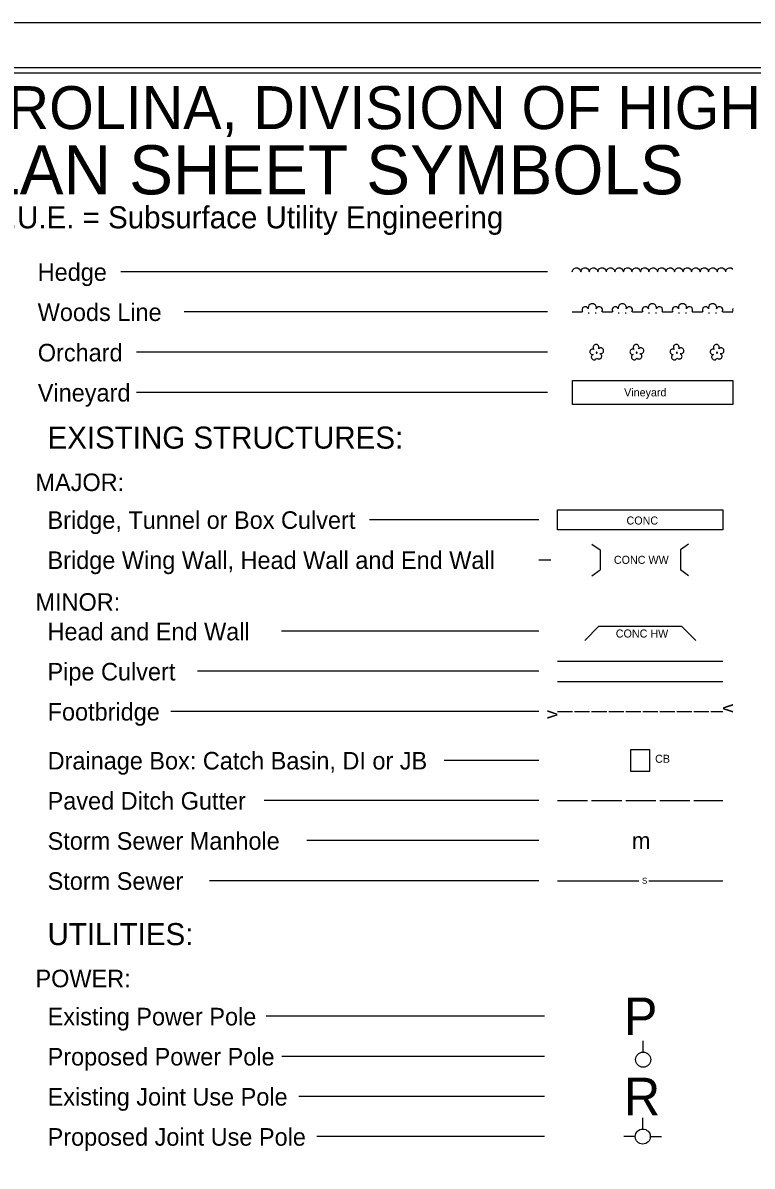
# Model space of a CAD drawing. Extents: x 872928 to 873392, y 373968 to 374173.
# Drawn here: x 872946.93 to 872954.2, y 374081.15 to 374092.55 of the extents above; entities that cross this region are included whole.
import ezdxf

# ---------------------------------------------------------------- set-up
doc = ezdxf.new("R2010")
doc.units = 0
for name, color, linetype in [('Sheet Cutting Line CELL', 7, 'Continuous'), ('Sheet Plot Border Inside CELL', 7, 'Continuous'), ('Sheet Plot Border Outside CELL', 7, 'Continuous'), ('Sheet Symbology CELL', 7, 'Continuous')]:
    doc.layers.add(name, color=color, linetype=linetype)

msp = doc.modelspace()

# ---------------------------------------------------------------- linework, layer by layer
at = {"layer": 'Sheet Cutting Line CELL'}
msp.add_line((872962.151, 374092.547), (872928.471, 374092.547), dxfattribs=at)
at = {"layer": 'Sheet Plot Border Inside CELL'}
msp.add_lwpolyline([(872928.731, 374070.996), (872962.061, 374070.996), (872962.061, 374092.098), (872928.731, 374092.098)], close=True, dxfattribs=at)
at = {"layer": 'Sheet Plot Border Outside CELL'}
msp.add_lwpolyline([(872928.471, 374070.547), (872962.151, 374070.547), (872962.151, 374092.547), (872928.471, 374092.547)], close=True, dxfattribs=at)
at = {"layer": 'Sheet Symbology CELL'}
for p, q in [((872952.157, 374090.064), (872947.903, 374090.064)), ((872952.405, 374090.064), (872952.411, 374090.083)), ((872952.411, 374090.083), (872952.423, 374090.096)), ((872952.423, 374090.096), (872952.439, 374090.105)), ((872952.439, 374090.105), (872952.458, 374090.105)), ((872952.458, 374090.105), (872952.474, 374090.095)), ((872952.474, 374090.095), (872952.485, 374090.082)), ((872952.485, 374090.082), (872952.489, 374090.065)), ((872952.49, 374090.064), (872952.496, 374090.083)), ((872952.496, 374090.083), (872952.508, 374090.096)), ((872952.508, 374090.096), (872952.524, 374090.105)), ((872952.524, 374090.105), (872952.543, 374090.105)), ((872952.543, 374090.105), (872952.559, 374090.095)), ((872952.559, 374090.095), (872952.57, 374090.082)), ((872952.57, 374090.082), (872952.574, 374090.065)), ((872952.575, 374090.064), (872952.581, 374090.083)), ((872952.581, 374090.083), (872952.593, 374090.096)), ((872952.593, 374090.096), (872952.609, 374090.105)), ((872952.609, 374090.105), (872952.628, 374090.105)), ((872952.628, 374090.105), (872952.644, 374090.095)), ((872952.644, 374090.095), (872952.655, 374090.082)), ((872952.655, 374090.082), (872952.659, 374090.065)), ((872952.66, 374090.064), (872952.666, 374090.083)), ((872952.666, 374090.083), (872952.678, 374090.096)), ((872952.678, 374090.096), (872952.694, 374090.105)), ((872952.694, 374090.105), (872952.713, 374090.105)), ((872952.713, 374090.105), (872952.729, 374090.095)), ((872952.729, 374090.095), (872952.74, 374090.082)), ((872952.74, 374090.082), (872952.744, 374090.065)), ((872952.745, 374090.064), (872952.751, 374090.083)), ((872952.751, 374090.083), (872952.763, 374090.096)), ((872952.763, 374090.096), (872952.779, 374090.105)), ((872952.779, 374090.105), (872952.798, 374090.105)), ((872952.798, 374090.105), (872952.814, 374090.095)), ((872952.814, 374090.095), (872952.825, 374090.082)), ((872952.825, 374090.082), (872952.829, 374090.065)), ((872952.83, 374090.064), (872952.836, 374090.083)), ((872952.836, 374090.083), (872952.848, 374090.096)), ((872952.848, 374090.096), (872952.864, 374090.105)), ((872952.864, 374090.105), (872952.883, 374090.105)), ((872952.883, 374090.105), (872952.899, 374090.095)), ((872952.899, 374090.095), (872952.91, 374090.082)), ((872952.91, 374090.082), (872952.914, 374090.065)), ((872952.915, 374090.064), (872952.921, 374090.083)), ((872952.921, 374090.083), (872952.933, 374090.096)), ((872952.933, 374090.096), (872952.949, 374090.105)), ((872952.949, 374090.105), (872952.968, 374090.105)), ((872952.968, 374090.105), (872952.984, 374090.095)), ((872952.984, 374090.095), (872952.995, 374090.082)), ((872952.995, 374090.082), (872952.999, 374090.065)), ((872953, 374090.064), (872953.006, 374090.083)), ((872953.006, 374090.083), (872953.018, 374090.096)), ((872953.018, 374090.096), (872953.034, 374090.105)), ((872953.034, 374090.105), (872953.053, 374090.105)), ((872953.053, 374090.105), (872953.069, 374090.095)), ((872953.069, 374090.095), (872953.08, 374090.082)), ((872953.08, 374090.082), (872953.084, 374090.065)), ((872953.085, 374090.064), (872953.091, 374090.083)), ((872953.091, 374090.083), (872953.103, 374090.096)), ((872953.103, 374090.096), (872953.119, 374090.105)), ((872953.119, 374090.105), (872953.138, 374090.105)), ((872953.138, 374090.105), (872953.154, 374090.095)), ((872953.154, 374090.095), (872953.165, 374090.082)), ((872953.165, 374090.082), (872953.169, 374090.065)), ((872953.17, 374090.064), (872953.176, 374090.083)), ((872953.176, 374090.083), (872953.188, 374090.096)), ((872953.188, 374090.096), (872953.204, 374090.105)), ((872953.204, 374090.105), (872953.223, 374090.105)), ((872953.223, 374090.105), (872953.239, 374090.095)), ((872953.239, 374090.095), (872953.25, 374090.082)), ((872953.25, 374090.082), (872953.254, 374090.065)), ((872953.255, 374090.064), (872953.261, 374090.083)), ((872953.261, 374090.083), (872953.273, 374090.096)), ((872953.273, 374090.096), (872953.289, 374090.105)), ((872953.289, 374090.105), (872953.308, 374090.105)), ((872953.308, 374090.105), (872953.324, 374090.095)), ((872953.324, 374090.095), (872953.335, 374090.082)), ((872953.335, 374090.082), (872953.339, 374090.065)), ((872953.34, 374090.064), (872953.346, 374090.083)), ((872953.346, 374090.083), (872953.358, 374090.096)), ((872953.358, 374090.096), (872953.374, 374090.105)), ((872953.374, 374090.105), (872953.393, 374090.105)), ((872953.393, 374090.105), (872953.409, 374090.095)), ((872953.409, 374090.095), (872953.42, 374090.082)), ((872953.42, 374090.082), (872953.424, 374090.065)), ((872953.425, 374090.064), (872953.431, 374090.083)), ((872953.431, 374090.083), (872953.443, 374090.096)), ((872953.443, 374090.096), (872953.459, 374090.105)), ((872953.459, 374090.105), (872953.478, 374090.105)), ((872953.478, 374090.105), (872953.494, 374090.095)), ((872953.494, 374090.095), (872953.505, 374090.082)), ((872953.505, 374090.082), (872953.509, 374090.065)), ((872953.51, 374090.064), (872953.516, 374090.083)), ((872953.516, 374090.083), (872953.528, 374090.096)), ((872953.528, 374090.096), (872953.544, 374090.105)), ((872953.544, 374090.105), (872953.563, 374090.105)), ((872953.563, 374090.105), (872953.579, 374090.095)), ((872953.579, 374090.095), (872953.59, 374090.082)), ((872953.59, 374090.082), (872953.594, 374090.065)), ((872953.595, 374090.064), (872953.601, 374090.083)), ((872953.601, 374090.083), (872953.613, 374090.096)), ((872953.613, 374090.096), (872953.629, 374090.105)), ((872953.629, 374090.105), (872953.648, 374090.105)), ((872953.648, 374090.105), (872953.664, 374090.095)), ((872953.664, 374090.095), (872953.675, 374090.082)), ((872953.675, 374090.082), (872953.679, 374090.065)), ((872953.68, 374090.064), (872953.686, 374090.083)), ((872953.686, 374090.083), (872953.698, 374090.096)), ((872953.698, 374090.096), (872953.714, 374090.105)), ((872953.714, 374090.105), (872953.733, 374090.105)), ((872953.733, 374090.105), (872953.749, 374090.095)), ((872953.749, 374090.095), (872953.76, 374090.082)), ((872953.76, 374090.082), (872953.764, 374090.065)), ((872953.765, 374090.064), (872953.771, 374090.083)), ((872953.771, 374090.083), (872953.783, 374090.096)), ((872953.783, 374090.096), (872953.799, 374090.105)), ((872953.799, 374090.105), (872953.818, 374090.105)), ((872953.818, 374090.105), (872953.834, 374090.095)), ((872953.834, 374090.095), (872953.845, 374090.082)), ((872953.845, 374090.082), (872953.849, 374090.065)), ((872953.85, 374090.064), (872953.856, 374090.083)), ((872953.856, 374090.083), (872953.868, 374090.096)), ((872953.868, 374090.096), (872953.884, 374090.105)), ((872953.884, 374090.105), (872953.903, 374090.105)), ((872953.903, 374090.105), (872953.919, 374090.095)), ((872953.919, 374090.095), (872953.93, 374090.082)), ((872953.93, 374090.082), (872953.934, 374090.065)), ((872953.935, 374090.064), (872953.941, 374090.083)), ((872953.941, 374090.083), (872953.953, 374090.096)), ((872953.953, 374090.096), (872953.969, 374090.105)), ((872953.969, 374090.105), (872953.988, 374090.105)), ((872953.988, 374090.105), (872954.004, 374090.095)), ((872954.004, 374090.095), (872954.005, 374090.094)), ((872952.157, 374089.664), (872948.534, 374089.664)), ((872952.405, 374089.664), (872952.505, 374089.664)), ((872952.705, 374089.664), (872952.805, 374089.664)), ((872953.005, 374089.664), (872953.105, 374089.664)), ((872953.305, 374089.664), (872953.405, 374089.664)), ((872953.605, 374089.664), (872953.705, 374089.664)), ((872953.905, 374089.664), (872954.005, 374089.664)), ((872952.564, 374089.654), (872952.574, 374089.654)), ((872952.634, 374089.654), (872952.644, 374089.654)), ((872952.864, 374089.654), (872952.874, 374089.654)), ((872952.934, 374089.654), (872952.944, 374089.654)), ((872953.164, 374089.654), (872953.174, 374089.654)), ((872953.234, 374089.654), (872953.244, 374089.654)), ((872953.464, 374089.654), (872953.474, 374089.654)), ((872953.534, 374089.654), (872953.544, 374089.654)), ((872953.764, 374089.654), (872953.774, 374089.654)), ((872953.834, 374089.654), (872953.844, 374089.654)), ((872952.158, 374089.262), (872948.059, 374089.262)), ((872952.158, 374088.862), (872948.059, 374088.862)), ((872952.072, 374087.592), (872950.383, 374087.592)), ((872952.601, 374087.349), (872952.683, 374087.292)), ((872952.683, 374087.292), (872952.683, 374087.092)), ((872953.565, 374087.349), (872953.483, 374087.292)), ((872953.483, 374087.292), (872953.483, 374087.092)), ((872952.072, 374087.192), (872952.191, 374087.192)), ((872952.601, 374087.034), (872952.683, 374087.092)), ((872953.565, 374087.034), (872953.483, 374087.092)), ((872952.072, 374086.48), (872949.506, 374086.48)), ((872952.529, 374086.389), (872952.67, 374086.53)), ((872952.67, 374086.53), (872953.495, 374086.53)), ((872953.495, 374086.53), (872953.637, 374086.389)), ((872952.258, 374086.18), (872953.908, 374086.18)), ((872952.072, 374086.08), (872948.668, 374086.08)), ((872952.258, 374085.98), (872953.908, 374085.98)), ((872952.072, 374085.68), (872948.402, 374085.68)), ((872952.258, 374085.68), (872952.408, 374085.68)), ((872952.428, 374085.68), (872952.578, 374085.68)), ((872952.598, 374085.68), (872952.748, 374085.68)), ((872952.768, 374085.68), (872952.918, 374085.68)), ((872952.938, 374085.68), (872953.088, 374085.68)), ((872953.108, 374085.68), (872953.258, 374085.68)), ((872953.278, 374085.68), (872953.428, 374085.68)), ((872953.448, 374085.68), (872953.598, 374085.68)), ((872953.618, 374085.68), (872953.768, 374085.68)), ((872953.788, 374085.68), (872953.908, 374085.68)), ((872952.072, 374085.192), (872951.128, 374085.192)), ((872952.072, 374084.792), (872949.333, 374084.792)), ((872952.258, 374084.792), (872952.558, 374084.792)), ((872952.598, 374084.792), (872952.898, 374084.792)), ((872952.938, 374084.792), (872953.238, 374084.792)), ((872953.278, 374084.792), (872953.578, 374084.792)), ((872953.618, 374084.792), (872953.908, 374084.792)), ((872952.072, 374084.392), (872949.758, 374084.392)), ((872952.072, 374083.992), (872948.788, 374083.992)), ((872952.258, 374083.992), (872953.068, 374083.992)), ((872953.168, 374083.992), (872953.908, 374083.992)), ((872952.127, 374082.64), (872949.353, 374082.64)), ((872953.112, 374082.282), (872953.112, 374082.395)), ((872952.127, 374082.24), (872949.509, 374082.24)), ((872952.127, 374081.84), (872949.677, 374081.84)), ((872953.108, 374081.515), (872953.108, 374081.628)), ((872952.127, 374081.44), (872949.857, 374081.44)), ((872953.033, 374081.44), (872952.92, 374081.44)), ((872953.183, 374081.44), (872953.295, 374081.44))]:
    msp.add_line(p, q, dxfattribs=at)
for points in [[(872961.811, 374092.047), (872931.811, 374092.047), (872931.811, 374071.068), (872961.811, 374071.068)], [(872952.986, 374085.085), (872953.179, 374085.085), (872953.179, 374085.298), (872952.986, 374085.298)]]:
    msp.add_lwpolyline(points, close=True, dxfattribs=at)
for points in [[(872952.667, 374089.297), (872952.67, 374089.303), (872952.671, 374089.309), (872952.67, 374089.315), (872952.669, 374089.321), (872952.666, 374089.326), (872952.663, 374089.331), (872952.658, 374089.335), (872952.653, 374089.338), (872952.646, 374089.34), (872952.641, 374089.34), (872952.635, 374089.339), (872952.629, 374089.337), (872952.624, 374089.334), (872952.619, 374089.33), (872952.616, 374089.324), (872952.614, 374089.319), (872952.613, 374089.313), (872952.613, 374089.307), (872952.614, 374089.301), (872952.617, 374089.296), (872952.621, 374089.29), (872952.616, 374089.293), (872952.61, 374089.294), (872952.604, 374089.294), (872952.599, 374089.292), (872952.594, 374089.29), (872952.589, 374089.286), (872952.585, 374089.282), (872952.582, 374089.277), (872952.581, 374089.272), (872952.58, 374089.265), (872952.581, 374089.26), (872952.583, 374089.255), (872952.587, 374089.25), (872952.59, 374089.246), (872952.595, 374089.243), (872952.601, 374089.24), (872952.606, 374089.239), (872952.612, 374089.239), (872952.607, 374089.237), (872952.602, 374089.233), (872952.599, 374089.229), (872952.597, 374089.223), (872952.595, 374089.217), (872952.595, 374089.212), (872952.596, 374089.206), (872952.599, 374089.201), (872952.602, 374089.196), (872952.606, 374089.192), (872952.611, 374089.189), (872952.616, 374089.187), (872952.622, 374089.187), (872952.628, 374089.187), (872952.633, 374089.188), (872952.638, 374089.192), (872952.643, 374089.195), (872952.648, 374089.204)], [(872953.067, 374089.297), (872953.07, 374089.303), (872953.071, 374089.309), (872953.07, 374089.315), (872953.069, 374089.321), (872953.066, 374089.326), (872953.063, 374089.331), (872953.058, 374089.335), (872953.053, 374089.338), (872953.046, 374089.34), (872953.041, 374089.34), (872953.035, 374089.339), (872953.029, 374089.337), (872953.024, 374089.334), (872953.019, 374089.33), (872953.016, 374089.324), (872953.014, 374089.319), (872953.013, 374089.313), (872953.013, 374089.307), (872953.014, 374089.301), (872953.017, 374089.296), (872953.021, 374089.29), (872953.016, 374089.293), (872953.01, 374089.294), (872953.004, 374089.294), (872952.999, 374089.292), (872952.994, 374089.29), (872952.989, 374089.286), (872952.985, 374089.282), (872952.982, 374089.277), (872952.981, 374089.272), (872952.98, 374089.265), (872952.981, 374089.26), (872952.983, 374089.255), (872952.987, 374089.25), (872952.99, 374089.246), (872952.995, 374089.243), (872953.001, 374089.24), (872953.006, 374089.239), (872953.012, 374089.239), (872953.007, 374089.237), (872953.002, 374089.233), (872952.999, 374089.229), (872952.997, 374089.223), (872952.995, 374089.217), (872952.995, 374089.212), (872952.996, 374089.206), (872952.999, 374089.201), (872953.002, 374089.196), (872953.006, 374089.192), (872953.011, 374089.189), (872953.016, 374089.187), (872953.022, 374089.187), (872953.028, 374089.187), (872953.033, 374089.188), (872953.038, 374089.192), (872953.043, 374089.195), (872953.048, 374089.204)], [(872953.467, 374089.297), (872953.47, 374089.303), (872953.471, 374089.309), (872953.47, 374089.315), (872953.469, 374089.321), (872953.466, 374089.326), (872953.463, 374089.331), (872953.458, 374089.335), (872953.453, 374089.338), (872953.446, 374089.34), (872953.441, 374089.34), (872953.435, 374089.339), (872953.429, 374089.337), (872953.424, 374089.334), (872953.419, 374089.33), (872953.416, 374089.324), (872953.414, 374089.319), (872953.413, 374089.313), (872953.413, 374089.307), (872953.414, 374089.301), (872953.417, 374089.296), (872953.421, 374089.29), (872953.416, 374089.293), (872953.41, 374089.294), (872953.404, 374089.294), (872953.399, 374089.292), (872953.394, 374089.29), (872953.389, 374089.286), (872953.385, 374089.282), (872953.382, 374089.277), (872953.381, 374089.272), (872953.38, 374089.265), (872953.381, 374089.26), (872953.383, 374089.255), (872953.387, 374089.25), (872953.39, 374089.246), (872953.395, 374089.243), (872953.401, 374089.24), (872953.406, 374089.239), (872953.412, 374089.239), (872953.407, 374089.237), (872953.402, 374089.233), (872953.399, 374089.229), (872953.397, 374089.223), (872953.395, 374089.217), (872953.395, 374089.212), (872953.396, 374089.206), (872953.399, 374089.201), (872953.402, 374089.196), (872953.406, 374089.192), (872953.411, 374089.189), (872953.416, 374089.187), (872953.422, 374089.187), (872953.428, 374089.187), (872953.433, 374089.188), (872953.438, 374089.192), (872953.443, 374089.195), (872953.448, 374089.204)], [(872953.867, 374089.297), (872953.87, 374089.303), (872953.871, 374089.309), (872953.87, 374089.315), (872953.869, 374089.321), (872953.866, 374089.326), (872953.863, 374089.331), (872953.858, 374089.335), (872953.853, 374089.338), (872953.846, 374089.34), (872953.841, 374089.34), (872953.835, 374089.339), (872953.829, 374089.337), (872953.824, 374089.334), (872953.819, 374089.33), (872953.816, 374089.324), (872953.814, 374089.319), (872953.813, 374089.313), (872953.813, 374089.307), (872953.814, 374089.301), (872953.817, 374089.296), (872953.821, 374089.29), (872953.816, 374089.293), (872953.81, 374089.294), (872953.804, 374089.294), (872953.799, 374089.292), (872953.794, 374089.29), (872953.789, 374089.286), (872953.785, 374089.282), (872953.782, 374089.277), (872953.781, 374089.272), (872953.78, 374089.265), (872953.781, 374089.26), (872953.783, 374089.255), (872953.787, 374089.25), (872953.79, 374089.246), (872953.795, 374089.243), (872953.801, 374089.24), (872953.806, 374089.239), (872953.812, 374089.239), (872953.807, 374089.237), (872953.802, 374089.233), (872953.799, 374089.229), (872953.797, 374089.223), (872953.795, 374089.217), (872953.795, 374089.212), (872953.796, 374089.206), (872953.799, 374089.201), (872953.802, 374089.196), (872953.806, 374089.192), (872953.811, 374089.189), (872953.816, 374089.187), (872953.822, 374089.187), (872953.828, 374089.187), (872953.833, 374089.188), (872953.838, 374089.192), (872953.843, 374089.195), (872953.848, 374089.204)], [(872952.65, 374089.262), (872952.647, 374089.262), (872952.645, 374089.261), (872952.643, 374089.26), (872952.643, 374089.257), (872952.643, 374089.255), (872952.645, 374089.253), (872952.648, 374089.253), (872952.65, 374089.253), (872952.652, 374089.255), (872952.653, 374089.258), (872952.652, 374089.26), (872952.65, 374089.262)], [(872952.648, 374089.204), (872952.66, 374089.197), (872952.666, 374089.195), (872952.672, 374089.194), (872952.678, 374089.195), (872952.683, 374089.197), (872952.688, 374089.2), (872952.693, 374089.204), (872952.696, 374089.209), (872952.698, 374089.214), (872952.7, 374089.22), (872952.699, 374089.226), (872952.698, 374089.232), (872952.694, 374089.238), (872952.691, 374089.242), (872952.686, 374089.245), (872952.68, 374089.248), (872952.686, 374089.247), (872952.693, 374089.247), (872952.698, 374089.249), (872952.704, 374089.252), (872952.709, 374089.255), (872952.713, 374089.26), (872952.716, 374089.266), (872952.717, 374089.272), (872952.718, 374089.278), (872952.717, 374089.284), (872952.715, 374089.29), (872952.711, 374089.295), (872952.706, 374089.3), (872952.701, 374089.303), (872952.695, 374089.305), (872952.689, 374089.306), (872952.683, 374089.306), (872952.677, 374089.304), (872952.672, 374089.301), (872952.667, 374089.297)], [(872953.05, 374089.262), (872953.047, 374089.262), (872953.045, 374089.261), (872953.043, 374089.26), (872953.043, 374089.257), (872953.043, 374089.255), (872953.045, 374089.253), (872953.048, 374089.253), (872953.05, 374089.253), (872953.052, 374089.255), (872953.053, 374089.258), (872953.052, 374089.26), (872953.05, 374089.262)], [(872953.048, 374089.204), (872953.06, 374089.197), (872953.066, 374089.195), (872953.072, 374089.194), (872953.078, 374089.195), (872953.083, 374089.197), (872953.088, 374089.2), (872953.093, 374089.204), (872953.096, 374089.209), (872953.098, 374089.214), (872953.1, 374089.22), (872953.099, 374089.226), (872953.098, 374089.232), (872953.094, 374089.238), (872953.091, 374089.242), (872953.086, 374089.245), (872953.08, 374089.248), (872953.086, 374089.247), (872953.093, 374089.247), (872953.098, 374089.249), (872953.104, 374089.252), (872953.109, 374089.255), (872953.113, 374089.26), (872953.116, 374089.266), (872953.117, 374089.272), (872953.118, 374089.278), (872953.117, 374089.284), (872953.115, 374089.29), (872953.111, 374089.295), (872953.106, 374089.3), (872953.101, 374089.303), (872953.095, 374089.305), (872953.089, 374089.306), (872953.083, 374089.306), (872953.077, 374089.304), (872953.072, 374089.301), (872953.067, 374089.297)], [(872953.45, 374089.262), (872953.447, 374089.262), (872953.445, 374089.261), (872953.443, 374089.26), (872953.443, 374089.257), (872953.443, 374089.255), (872953.445, 374089.253), (872953.448, 374089.253), (872953.45, 374089.253), (872953.452, 374089.255), (872953.453, 374089.258), (872953.452, 374089.26), (872953.45, 374089.262)], [(872953.448, 374089.204), (872953.46, 374089.197), (872953.466, 374089.195), (872953.472, 374089.194), (872953.478, 374089.195), (872953.483, 374089.197), (872953.488, 374089.2), (872953.493, 374089.204), (872953.496, 374089.209), (872953.498, 374089.214), (872953.5, 374089.22), (872953.499, 374089.226), (872953.498, 374089.232), (872953.494, 374089.238), (872953.491, 374089.242), (872953.486, 374089.245), (872953.48, 374089.248), (872953.486, 374089.247), (872953.493, 374089.247), (872953.498, 374089.249), (872953.504, 374089.252), (872953.509, 374089.255), (872953.513, 374089.26), (872953.516, 374089.266), (872953.517, 374089.272), (872953.518, 374089.278), (872953.517, 374089.284), (872953.515, 374089.29), (872953.511, 374089.295), (872953.506, 374089.3), (872953.501, 374089.303), (872953.495, 374089.305), (872953.489, 374089.306), (872953.483, 374089.306), (872953.477, 374089.304), (872953.472, 374089.301), (872953.467, 374089.297)], [(872953.85, 374089.262), (872953.847, 374089.262), (872953.845, 374089.261), (872953.843, 374089.26), (872953.843, 374089.257), (872953.843, 374089.255), (872953.845, 374089.253), (872953.848, 374089.253), (872953.85, 374089.253), (872953.852, 374089.255), (872953.853, 374089.258), (872953.852, 374089.26), (872953.85, 374089.262)], [(872953.848, 374089.204), (872953.86, 374089.197), (872953.866, 374089.195), (872953.872, 374089.194), (872953.878, 374089.195), (872953.883, 374089.197), (872953.888, 374089.2), (872953.893, 374089.204), (872953.896, 374089.209), (872953.898, 374089.214), (872953.9, 374089.22), (872953.899, 374089.226), (872953.898, 374089.232), (872953.894, 374089.238), (872953.891, 374089.242), (872953.886, 374089.245), (872953.88, 374089.248), (872953.886, 374089.247), (872953.893, 374089.247), (872953.898, 374089.249), (872953.904, 374089.252), (872953.909, 374089.255), (872953.913, 374089.26), (872953.916, 374089.266), (872953.917, 374089.272), (872953.918, 374089.278), (872953.917, 374089.284), (872953.915, 374089.29), (872953.911, 374089.295), (872953.906, 374089.3), (872953.901, 374089.303), (872953.895, 374089.305), (872953.889, 374089.306), (872953.883, 374089.306), (872953.877, 374089.304), (872953.872, 374089.301), (872953.867, 374089.297)], [(872952.406, 374088.982), (872954.006, 374088.982), (872954.006, 374088.742), (872952.406, 374088.742), (872952.406, 374088.982)], [(872952.258, 374087.692), (872953.908, 374087.692), (872953.908, 374087.492), (872952.258, 374087.492), (872952.258, 374087.692)]]:
    msp.add_lwpolyline(points, dxfattribs=at)
for centre in [(872953.112, 374082.207), (872953.108, 374081.44)]:
    msp.add_circle(centre, 0.075, dxfattribs=at)
for centre, radius, start, end in [((872952.534, 374089.685), 0.0316, 18.435, 219.2315), ((872952.604, 374089.705), 0.0412, 345.9638, 194.0362), ((872952.674, 374089.685), 0.0316, 320.7685, 161.5651), ((872952.834, 374089.685), 0.0316, 18.435, 219.2315), ((872952.904, 374089.705), 0.0412, 345.9638, 194.0362), ((872952.974, 374089.685), 0.0316, 320.7685, 161.5651), ((872953.134, 374089.685), 0.0316, 18.435, 219.2315), ((872953.204, 374089.705), 0.0412, 345.9638, 194.0362), ((872953.274, 374089.685), 0.0316, 320.7685, 161.5651), ((872953.434, 374089.685), 0.0316, 18.435, 219.2315), ((872953.504, 374089.705), 0.0412, 345.9638, 194.0362), ((872953.574, 374089.685), 0.0316, 320.7685, 161.5651), ((872953.734, 374089.685), 0.0316, 18.435, 219.2315), ((872953.804, 374089.705), 0.0412, 345.9638, 194.0362), ((872953.874, 374089.685), 0.0316, 320.7685, 161.5651), ((872954.034, 374089.685), 0.0316, 156.251, 203.749)]:
    msp.add_arc(centre, radius, start, end, dxfattribs=at)

# ---------------------------------------------------------------- texts
for s, height, p in [('STATE OF NORTH CAROLINA, DIVISION OF HIGHWAYS', 0.42838, (872940.823, 374091.488)), ('CONVENTIONAL  PLAN SHEET SYMBOLS', 0.48961, (872940.564, 374090.837)), ('Hedge', 0.175, (872947.074, 374089.974)), ('Woods Line', 0.175, (872947.074, 374089.574)), ('Orchard', 0.175, (872947.075, 374089.171)), ('Vineyard', 0.175, (872947.075, 374088.771)), ('EXISTING STRUCTURES:', 0.22, (872947.172, 374088.301)), ('MAJOR:', 0.175, (872947.052, 374087.878)), ('Bridge, Tunnel or Box Culvert', 0.175, (872947.172, 374087.501)), ('CONC', 0.08, (872952.946, 374087.544)), ('Bridge Wing Wall, Head Wall and End Wall', 0.175, (872947.172, 374087.101)), ('MINOR:', 0.175, (872947.052, 374086.684)), ('Head and End Wall', 0.175, (872947.172, 374086.389)), ('Pipe Culvert', 0.175, (872947.172, 374085.989)), ('Footbridge', 0.175, (872947.173, 374085.589)), ('Drainage Box: Catch Basin, DI or JB', 0.175, (872947.173, 374085.101)), ('Paved Ditch Gutter', 0.175, (872947.173, 374084.701)), ('Storm Sewer Manhole', 0.175, (872947.173, 374084.301)), ('m', 0.165, (872953, 374084.309)), ('Storm Sewer', 0.175, (872947.173, 374083.901)), ('S', 0.06, (872953.1, 374083.962)), ('UTILITIES:', 0.22, (872947.172, 374083.349)), ('POWER:', 0.175, (872947.052, 374082.929)), ('P', 0.375, (872952.92, 374082.452)), ('Existing Power Pole', 0.175, (872947.173, 374082.549)), ('Proposed Power Pole', 0.175, (872947.173, 374082.149)), ('R', 0.375, (872952.92, 374081.652)), ('Existing Joint Use Pole', 0.175, (872947.173, 374081.749)), ('Proposed Joint Use Pole', 0.175, (872947.173, 374081.349))]:
    msp.add_text(s, height=height, dxfattribs=at).set_placement(p)
for s, height, rotation, p in [('*S.U.E. = Subsurface Utility Engineering', 0.22, 360, (872946.476, 374090.498)), ('Vineyard', 0.08, 0, (872952.922, 374088.822)), ('CONC WW', 0.08, 0, (872952.82, 374087.152)), ('CONC HW', 0.08, 360, (872952.839, 374086.417)), ('v', 0.132, 89.7591, (872952.257, 374085.605)), ('v', 0.132, 270.2409, (872953.907, 374085.755)), ('CB', 0.08, 360, (872953.231, 374085.168))]:
    msp.add_text(s, height=height, rotation=rotation, dxfattribs=at).set_placement(p)

doc.saveas('drawing.dxf')
